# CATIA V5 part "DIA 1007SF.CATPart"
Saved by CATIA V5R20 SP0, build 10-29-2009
Part number: DIA 1007SF
Revision: ANY
Definition: UNKNOWN
Nomenclature: DIA 1007SF
Source: Unknown
Bounding box of the stored display mesh (mm): x -5.35 to 5.35, y -17 to 0, z -5.35 to 5.35
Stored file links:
  C:\Users\Utente\Desktop\IO LAVORO\3D X SITO CF\CUMSA\3D files FA\FA 200710-21\DIA 1007SF.CATPart

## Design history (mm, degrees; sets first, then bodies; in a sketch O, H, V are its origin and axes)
Body1 "Cortar-Extruir1" (main body)
  Solid1: solid without history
